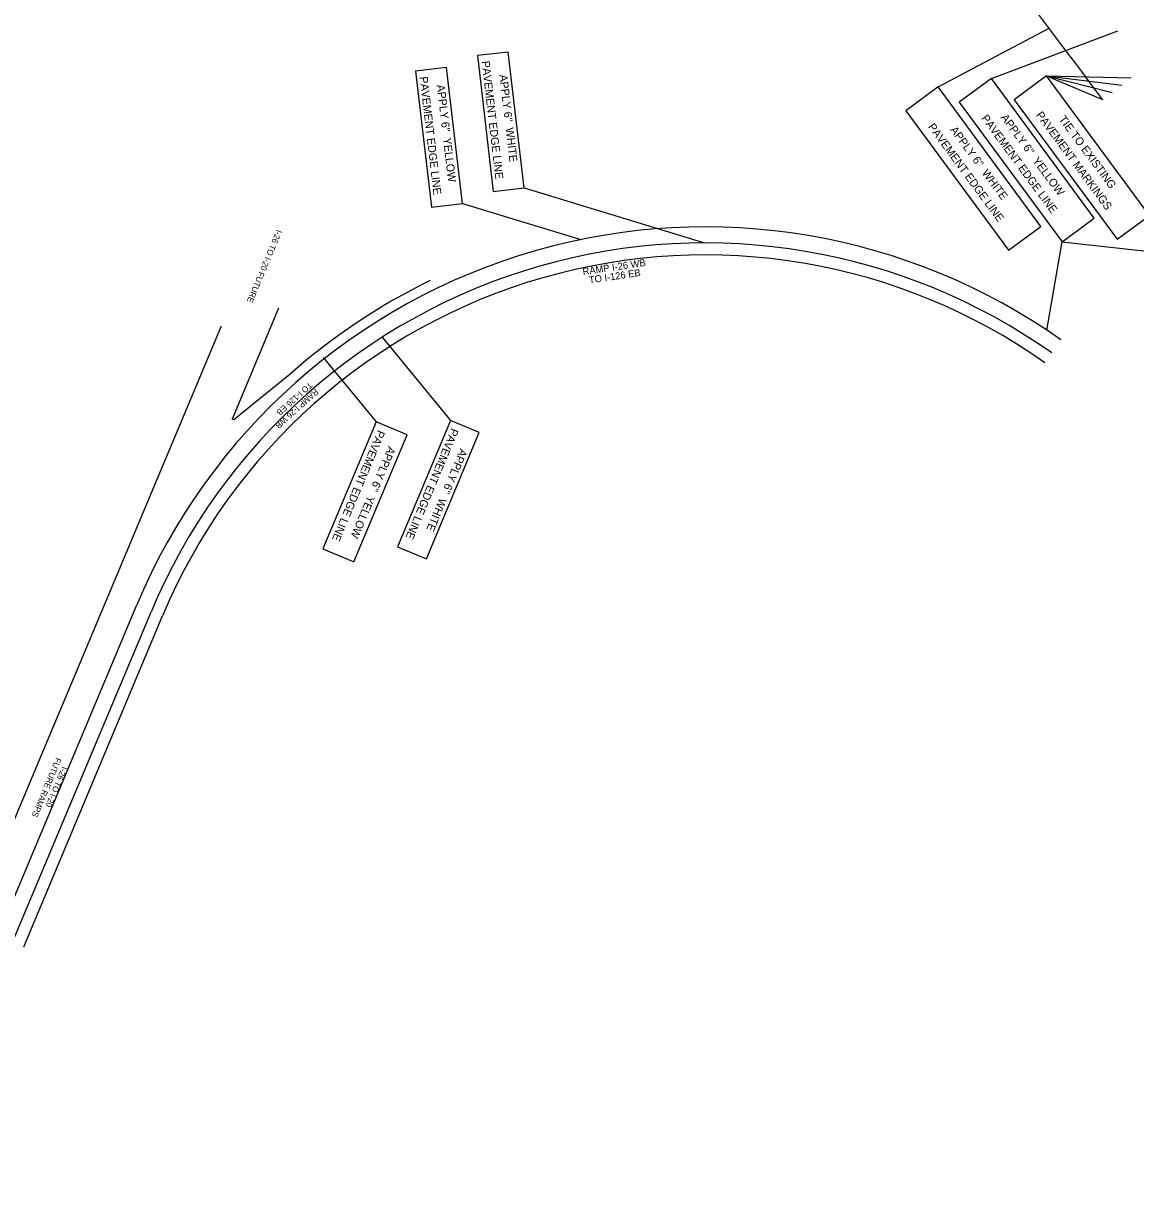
# Model space of a CAD drawing. Extents: x 1966013 to 1974896, y 789499 to 804826.
# Drawn here: x 1968743 to 1969854, y 796603 to 797784 of the extents above; entities that cross this region are included whole.
import ezdxf

# ---------------------------------------------------------------- set-up
doc = ezdxf.new("R2010")
doc.units = 0
for name, color, linetype in [('RD_EX_H2O_BlueLn', 7, 'Continuous'), ('RD_HC_Cl', 7, 'Continuous'), ('RD_HC_CL_Rel', 7, 'Continuous'), ('RD_PD_ALT5_CL', 7, 'Continuous'), ('RD_PD_MedBWall', 7, 'Continuous')]:
    doc.layers.add(name, color=color, linetype=linetype)

msp = doc.modelspace()

# ---------------------------------------------------------------- linework, layer by layer
at = {"layer": 'RD_EX_H2O_BlueLn'}
for p, q in [((1969657, 797720.4), (1969767.4, 797778.8)), ((1969710.3, 797728.9), (1969836.7, 797776.4)), ((1969765.4, 797731.4), (1969850.1, 797729.5)), ((1969765.4, 797731.4), (1969840.6, 797722.3)), ((1969765.4, 797731.4), (1969831, 797715)), ((1969765.4, 797731.4), (1969821.5, 797707.8)), ((1969243.7, 797619.6), (1969423.6, 797564.6)), ((1969181.8, 797604), (1969300, 797567.9)), ((1969765.7, 797477.4), (1969781, 797565.7)), ((1969781, 797565.7), (1969995.6, 797542.2)), ((1969101.8, 797470.3), (1969170, 797387.2)), ((1969042.8, 797450.1), (1969095.6, 797385.7))]:
    msp.add_line(p, q, dxfattribs=at)
for points in [[(1969196.8, 797751.7), (1969212.7, 797615.9), (1969243.7, 797619.6), (1969227.7, 797755.3)], [(1969134.9, 797736.1), (1969150.8, 797600.4), (1969181.8, 797604), (1969165.8, 797739.8)], [(1969678.1, 797705.2), (1969781, 797565.7), (1969813.1, 797589.4), (1969710.3, 797728.9)], [(1969733.2, 797707.7), (1969836, 797568.2), (1969868.2, 797591.9), (1969765.4, 797731.4)], [(1969624.8, 797696.7), (1969727.6, 797557.2), (1969759.8, 797580.9), (1969657, 797720.4)], [(1969170, 797387.2), (1969117.1, 797261.1), (1969145.8, 797249.1), (1969198.7, 797375.1)], [(1969095.6, 797385.7), (1969042.4, 797259.1), (1969073.3, 797246.1), (1969126.5, 797372.8)]]:
    msp.add_lwpolyline(points, close=True, dxfattribs=at)
at = {"layer": 'RD_HC_Cl'}
for p, q in [((1968998.2, 797499.5), (1968951.7, 797388.6)), ((1968940.8, 797481.5), (1968572.3, 796603)), ((1969009.8, 797433.6), (1968953.5, 797387.8)), ((1968953.5, 797387.8), (1968951.7, 797388.6)), ((1968743.5, 796861.2), (1968882.2, 797192))]:
    msp.add_line(p, q, dxfattribs=at)
for radius, start, end in [(588, 54.7761, 157.246), (626, 116.037, 131.4818)]:
    msp.add_arc((1969424.5, 796964.6), radius, start, end, dxfattribs=at)
at = {"layer": 'RD_PD_ALT5_CL'}
for p, q in [((1968717.7, 796872.2), (1968856.4, 797202.9)), ((1968732.5, 796866), (1968871.2, 797196.7))]:
    msp.add_line(p, q, dxfattribs=at)
for centre, radius, start, end in [((1978987, 804673.3), 11512, 215.37035, 217.23394), ((1969424.5, 796964.6), 616, 54.7761, 157.246), ((1969424.5, 796964.6), 600, 54.7761, 157.246)]:
    msp.add_arc(centre, radius, start, end, dxfattribs=at)

# ---------------------------------------------------------------- texts
at = {"layer": 'RD_EX_H2O_BlueLn'}
for s, rotation, p in [('PAVEMENT EDGE LINE', 276.7064, (1969201, 797746)), ('PAVEMENT EDGE LINE', 276.7064, (1969139.1, 797730.4)), ("APPLY 6''  WHITE", 276.7064, (1969218.7, 797732.4)), ("APPLY 6''  YELLOW", 276.7064, (1969156.2, 797722.3)), ('PAVEMENT MARKINGS', 306.3977, (1969754.5, 797692.3)), ('PAVEMENT EDGE LINE', 306.3977, (1969646.6, 797680.5)), ('PAVEMENT EDGE LINE', 306.3977, (1969699.9, 797689.1)), ("APPLY 6''  YELLOW", 306.3977, (1969719.3, 797689.8)), ('TIE TO EXISTING', 306.3977, (1969777.3, 797688.2)), ("APPLY 6''  WHITE", 306.3977, (1969668.7, 797677.5)), ('PAVEMENT EDGE LINE', 247.246, (1969097.4, 797378.2)), ('PAVEMENT EDGE LINE', 247.246, (1969170.9, 797380.1)), ("APPLY 6''  YELLOW", 247.246, (1969107.9, 797362)), ("APPLY 6''  WHITE", 247.246, (1969179.6, 797359.6))]:
    msp.add_text(s, height=8, rotation=rotation, dxfattribs=at).set_placement(p)
at = {"layer": 'RD_HC_CL_Rel'}
for s, p in [('TO I-126 EB ', (1969028.7, 797425.9)), ('RAMP I-26 WB ', (1969034.7, 797419.2))]:
    msp.add_text(s, height=6, rotation=221.8685, dxfattribs=at).set_placement(p)
at = {"layer": 'RD_PD_MedBWall'}
for s, height, rotation, p in [('I-26 TO I-20 FUTURE', 6, 247.4075, (1968996.3, 797578.4)), ('RAMP I-26 WB', 7, 8.4273, (1969302.5, 797532.4)), ('TO I-126 EB', 7, 8.4273, (1969308.8, 797524)), ('FUTURE RAMPS ', 6, 247.4075, (1968775.8, 797050.9)), ('I-26 TO I-20 ', 6, 247.4075, (1968781.9, 797042.1))]:
    msp.add_text(s, height=height, rotation=rotation, dxfattribs=at).set_placement(p)

doc.saveas('drawing.dxf')
